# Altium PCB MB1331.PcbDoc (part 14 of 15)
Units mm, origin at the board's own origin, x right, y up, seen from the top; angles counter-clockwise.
Board outline 169.25 x 173.25 mm, 6 copper layers (Top Layer, Signal Layer 1, Signal Layer 2, Signal Layer 3, Signal Layer 4, Bottom Layer), stack 1.556 mm thick; 871 components, 699 nets, 3244 pads, 2370 vias.
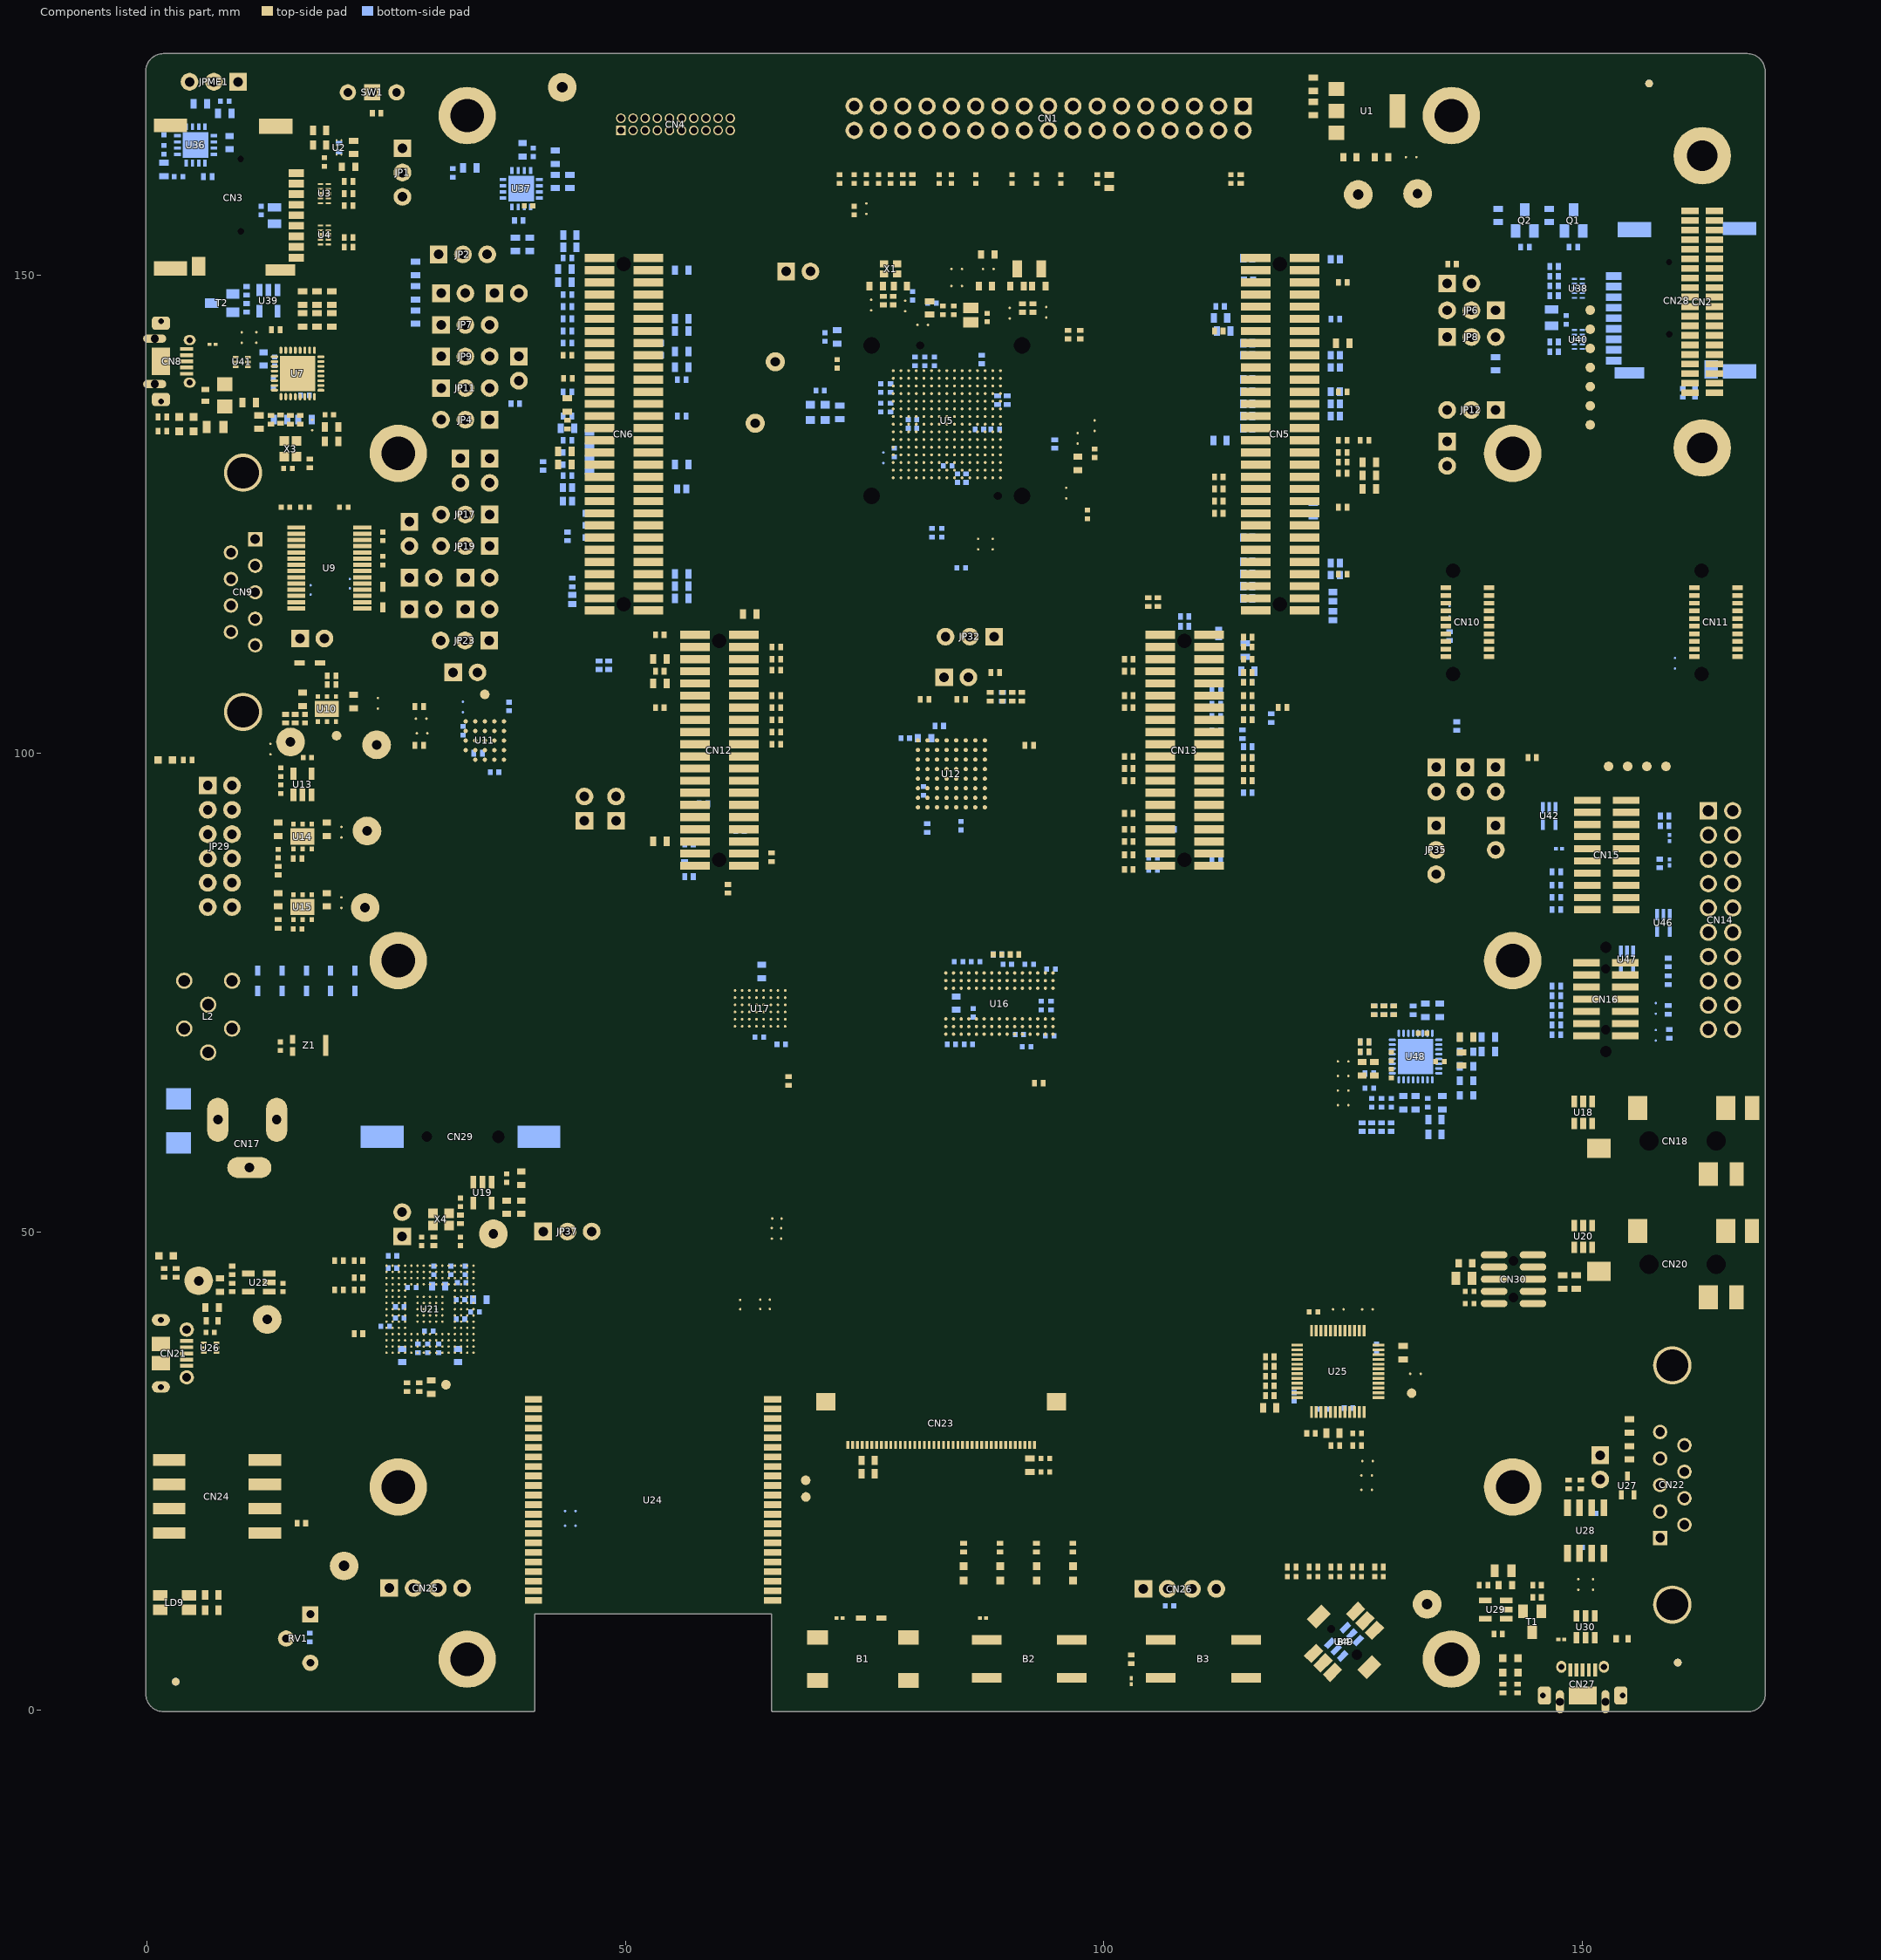
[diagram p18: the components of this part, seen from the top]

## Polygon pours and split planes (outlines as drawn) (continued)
5V_USB_HS on Top Layer "5V_USB_HS_L01_P1086" (solid, remove dead copper, pour order 1086): 5.969,134.874 6.604,134.874 6.731,134.747 6.731,134.493 6.731,132.842 6.604,132.715 5.715,132.715 5.588,132.842 5.588,133.35 5.588,134.747 5.715,134.874 5.969,134.874
NetC44_2 on Top Layer "NETC44_2_L01_P1068" (solid, remove dead copper, pour order 1068): 19.685,107.569 24.511,107.569 24.892,107.188 24.892,105.664 19.685,105.664 19.558,105.791 19.558,107.442
GND on Top Layer "GND_L01_P1080" (solid, remove dead copper, pour order 1080): 15.367,105.41 15.113,105.156 15.113,104.013 15.24,103.886 23.114,103.886 23.241,104.013 23.241,105.283 23.114,105.41
3V3_AO on Top Layer "3V3_AO_L01_P1084" (solid, remove dead copper, pour order 1084): 15.24,107.569 15.113,107.442 15.113,105.791 15.24,105.664 17.907,105.664 18.034,105.791 18.034,107.442 17.907,107.569
5V_D on Top Layer "5V_D_L01_P1087" (solid, remove dead copper, pour order 1087): 41.783,85.344 42.672,85.344 42.799,85.217 42.799,82.804 42.672,82.677 42.164,82.677 41.91,82.677 41.783,82.804 41.783,82.931 41.783,84.836
5V_USB_FS on Top Layer "5V_USB_FS_L01_P1090" (solid, remove dead copper, pour order 1090): 20.447,73.914 21.463,73.914 21.463,73.66 21.463,71.628 21.336,71.501 21.209,71.374 20.955,71.374 20.701,71.374 20.447,71.628 20.447,73.66
5V_USB_FS on Top Layer "5V_USB_FS_L01_P1093" (solid, remove dead copper, pour order 1093): 138.811,15.24 141.224,15.24 141.351,15.113 141.351,14.859 141.351,13.97 141.224,13.843 140.843,13.843 138.938,13.843 138.811,13.97 138.684,14.097 138.684,15.113 138.811,15.24
USB_OTG_FS_VBUS on Top Layer "USB_OTG_FS_VBUS_L01_P1095" (solid, remove dead copper, pour order 1095): 143.256,15.24 144.145,15.24 144.272,15.24 144.399,15.113 145.161,14.351 145.161,13.081 145.161,12.827 145.034,12.7 144.907,12.573 144.526,12.573 143.764,12.573 143.51,12.319 142.875,12.319 142.875,14.732 143.002,14.859
5V on Top Layer "5V_L01_P1098" (solid, remove dead copper, pour order 1098): 139.192,10.16 140.335,10.16 140.462,10.033 140.589,9.906 140.589,9.779 140.589,8.89 140.335,8.636 139.446,8.636 139.192,8.636 138.684,9.144 138.43,9.398 138.43,9.652 138.43,10.033 138.557,10.16 139.192,10.16
5V on Top Layer "5V_L01_P1101" (solid, remove dead copper, pour order 1101): 150.749,15.494 151.257,15.494 151.384,15.621 151.384,15.748 151.384,17.399 151.511,17.526 151.765,17.526 152.019,17.526 152.146,17.653 152.146,17.907 151.892,18.161 150.876,18.161 150.622,17.907 150.622,17.399 150.622,15.621 150.749,15.494
VDD_SMPS_IND_OUT on Top Layer "VDD_SMPS_IND_OUT_L01_P1069" (solid, remove dead copper, pour order 1069): 85.217,151.384 87.222,151.384 87.484,151.122 87.484,146.666 87.122,146.304 85.217,146.304 85.09,146.431 85.09,151.257
VDD_LDO on Top Layer "VDD_LDO_L01_P1074" (solid, remove dead copper, pour order 1074): 81.788,151.384 83.439,151.384 84.047,151.384 84.309,151.122 84.309,150.122 84.309,150.095 84.074,149.86 83.058,149.86 81.534,149.86 81.407,149.987 81.407,150.241 81.407,151.257 81.534,151.384 81.788,151.384
1V8_AO on Top Layer "1V8_AO_L01_P1081" (solid, remove dead copper, pour order 1081): 88.392,152.654 89.408,152.654 89.535,152.527 89.535,150.114 89.281,149.86 88.265,149.86 88.265,152.527
3V3_SMPS_IN on Top Layer "3V3_SMPS_IN_L01_P1085" (solid, remove dead copper, pour order 1085): 81.534,146.177 82.931,146.177 84.582,146.177 84.709,146.05 84.709,145.796 84.709,140.517 84.4,140.208 83.947,140.208 83.693,140.462 83.566,140.589 83.566,141.478 83.566,143.51 83.058,144.018 82.55,144.018 81.813,144.018 81.551,144.28 81.534,144.297 81.534,146.177
VCAP on Top Layer "VCAP_L01_P1088" (solid, remove dead copper, pour order 1088): 81.534,149.479 84.201,149.479 84.328,149.352 84.328,148.209 84.201,148.082 81.534,148.082 81.407,148.209 81.407,149.352
3V3_MCU on Top Layer "3V3_MCU_L01_P1091" (solid, remove dead copper, pour order 1091): 82.296,146.558 80.645,146.558 80.518,146.685 80.518,147.701 80.645,147.828 82.296,147.828 82.423,147.701 82.423,146.685
GND on Top Layer "GND_L01_P1070" (solid, remove dead copper, pour order 1070): 78,142 76.2,143.8 73.4,143.8 72.8,144.4 72.8,151.7 74,152.9 80.1,152.9 81.1,151.9 81.1,148.5 80.9,148.3 79.2,148.3 79,148.5 79,151.7 78.8,151.9 76.6,151.9 76.5,151.8 76.5,150.1 75.9,149.5 75.9,148.5 75.8,148.4 74.7,148.4 74.3,148 74.3,145.6 74.5,145.4 76.7,145.4 77.1,145 77.1,143.8 78.9,142
GND on Top Layer "GND_L01_P1075" (solid, remove dead copper, pour order 1075): 91,153 91.9,153 94.7,153 95.1,152.6 96.3,151.4 96.3,149.3 96.3,145.3 95.2,144.2 94.8,143.8 93.1,143.8 91.1,143.8 90.6,143.3 90.2,142.9 90.2,142.2 88.8,140.8 88.6,140.6 88.4,140.6 88.3,140.6 88.2,140.7 88.1,140.8 88.1,141.1 88.1,141.5 88.8,142.2 90.9,144.3 94.389,144.3 94.869,144.78 94.869,145.2 94.869,148.031 94.6,148.3 94.3,148.6 94.3,149.8 94.3,151.699 94.199,151.8 93.7,151.8 90.5,151.8 90.3,151.6 90.2,151.5 90.2,151.2 90.2,149.7 90.6,149.3 90.6,148.9 90.6,148.5 90.5,148.4 90.4,148.3 90.1,148.3 89.7,148.3 89.6,148.2 89.281,147.881 89.281,144.8 89.281,144.081 89,143.8 88.8,143.6 88.6,143.8 88.6,144.1 88.6,148.925 89.027,149.352 89.7,150.025 89.7,152.8 89.9,153 91,153
GND on Top Layer "GND_L01_P1152" (solid, remove dead copper, pour order 1152): 84.625,147.9 84.75,147.775 84.75,146.575 84.65,146.475 82.775,146.475 82.65,146.6 82.65,147.825 82.725,147.9
GND on Top Layer "GND_L01_P1154" (solid, remove dead copper, pour order 1154): 88.7,145.6 88.525,145.775 87.5,145.775 87.45,145.825 87.45,146.225 87.95,146.725 87.95,149.325 88.175,149.55 89.55,149.55 88.875,148.875 88.875,145.725 88.75,145.6
1V8_SW on Top Layer "1V8_SW_L01_P1073" (solid, remove dead copper, pour order 1073): 23.876,102.108 24.765,102.108 24.892,102.235 25.019,102.362 25.019,102.743 25.019,104.775 24.892,104.902 23.495,104.902 23.495,102.235 23.622,102.108 23.876,102.108
1V8_AO on Top Layer "1V8_AO_L01_P1079" (solid, remove dead copper, pour order 1079): 13.9,100.711 13.389,100.2 13.3,100.2 12.9,100.6 12.4,100.1 12.3,100.1 12,100.4 12,103.1 12.6,103.7 13.5,103.7 13.8,103.4 13.8,102.9 14,102.7 15.8,102.7 16,102.5 16.002,102 16.002,100.965 15.748,100.711
USB_OTG_FS_VBUS on Top Layer "USB_OTG_FS_VBUS_L01_P1115" (solid, remove dead copper, pour order 1115): 151.257,5.334 152.4,6.477 152.4,7.747 152.527,7.874 153.797,7.874 153.924,7.747 153.924,3.81 153.289,3.175 151.257,3.175
GND on Top Layer "GND_L01_P1118" (solid, remove dead copper, pour order 1118): 155.829,7.874 155.067,7.874 154.686,7.874 154.559,7.747 154.559,3.754 153.726,2.921 153.67,2.865 153.67,1.651 153.67,0.508 153.797,0.381 155.067,0.381 155.194,0.381 155.702,0.889 156.083,1.27 156.083,7.493 156.083,7.62 155.829,7.874
GND on Top Layer "GND_L01_P1121" (solid, remove dead copper, pour order 1121): 147.574,5.207 148.209,5.207 148.717,5.207 148.844,5.08 148.971,4.953 148.971,3.048 149.098,2.921 149.86,2.921 154.686,2.921 154.813,2.794 154.813,2.286 154.813,0.635 154.559,0.381 153.924,0.381 145.542,0.381 145.288,0.635 145.288,1.016 145.288,2.921 147.574,5.207
USB_OTG_FS_VBUS on Top Layer "USB_OTG_FS_VBUS_L01_P1127" (solid, remove dead copper, pour order 1127): 142.367,15.24 143.256,15.24 143.51,14.986 143.51,11.684 143.002,11.176 141.605,11.176 141.478,11.303 141.478,11.938 142.113,12.573 142.113,14.986
3V3_AO on Top Layer "3V3_AO_L01_P1131" (solid, remove dead copper, pour order 1131): 19.685,83.6 18.8,82.715 18.8,81.3 19,81.1 22.1,81.1 24.4,83.4 24.4,84.7 23.6,85.5 21.6,85.5 20.2,84.074 19.812,84.074 19.685,83.947
3V3_SW on Top Layer "3V3_SW_L01_P1133" (solid, remove dead copper, pour order 1133): 19.685,91.985 19.8,92.1 20.3,91.6 20.9,92.2 21.2,92.2 22.5,93.5 23.9,93.5 24.6,92.8 24.6,90.3 22.32,87.979 22.225,87.884 19.812,87.884 19.685,88.011
NetC53_2 on Top Layer "NETC53_2_L01_P1135" (solid, remove dead copper, pour order 1135): 16.256,86.614 20.828,86.614 21.082,86.36 21.082,84.963 16.129,84.963 16.002,85.09 16.002,86.36
5V_STLK on Top Layer "5V_STLK_L01_P1136" (solid, remove dead copper, pour order 1136): 14.859,40.159 14,39.3 11.6,39.3 10.9,40 10.9,41.904 12.065,43.104 12.065,43.942 12.192,44.069 14.732,44.069 14.859,43.942
3V3_STLK on Top Layer "3V3_STLK_L01_P1137" (solid, remove dead copper, pour order 1137): 37.405,48.2 35.4,48.2 34.5,49.1 34.5,50.7 35.687,51.9 35.687,53.467 35.814,53.594 36.576,53.594 36.703,53.467 36.703,52.832 36.957,52.578 39.497,52.578 39.624,52.451 39.624,50.419
GND on Top Layer "GND_L01_P1142" (solid, remove dead copper, pour order 1142): 18.034,84.709 13.335,84.709 13.208,84.582 13.208,84.328 13.208,83.439 13.335,83.312 13.462,83.185 15.494,83.185 19.177,83.185 19.304,83.312 19.304,83.566 19.304,84.582 19.177,84.709 18.034,84.709
5V_EXT_UNFILT on Top Layer "5V_EXT_UNFILT_L01_P1092" (solid, remove dead copper, pour order 1092): 14.986,73.406 15.621,72.771 15.621,69.85 15.367,69.596 8.636,69.596 8.128,70.104 8.128,73.025 8.509,73.406
5V_EXT_CONN on Top Layer "5V_EXT_CONN_L01_P1094" (solid, remove dead copper, pour order 1094): 21.082,58.928 21.59,59.436 21.59,69.596 19.812,71.374 17.78,71.374 17.272,70.866 17.272,65.405 16.764,64.897 12.573,64.897 12.065,64.389 12.065,59.182 12.319,58.928
GND_EXT_UNFILT on Top Layer "GND_EXT_UNFILT_L01_P1097" (solid, remove dead copper, pour order 1097): 12.573,54.991 3.302,54.991 2.54,55.753 2.54,56.134 2.54,66.294 3.175,66.929 3.429,67.183 3.81,67.183 6.985,67.183 7.874,68.072 9.144,69.342 14.605,69.342 15.494,69.342 15.621,69.215 15.621,69.088 15.621,65.786 15.367,65.532 14.605,65.532 11.811,65.532 11.303,65.024 11.049,64.77 11.049,64.643 11.049,58.674 11.43,58.293 11.811,58.293 13.081,58.293 13.462,57.912 13.462,57.531 13.462,55.245 13.208,54.991 12.573,54.991
5V_USB_CHGR on Top Layer "5V_USB_CHGR_L01_P1132" (solid, remove dead copper, pour order 1132): 3.524,38.386 5.143,38.386 5.558,38.8 6.257,38.8 6.477,39.02 6.572,39.02 6.572,42.481 6.953,42.862 10.763,42.862 11.239,43.339 11.239,44.005 11.144,44.101 5.715,44.101 5.429,43.815 5.429,39.719 4.667,38.957 3.524,38.957 3.429,38.862 3.429,38.481
5V on Top Layer "5V_L01_P1145" (solid, remove dead copper, pour order 1145): 8.763,82.931 10.668,82.931 11.557,82.931 11.811,83.185 11.811,83.566 11.811,97.409 11.557,97.663 8.89,97.663 8.255,97.663 8.001,97.409 8.001,96.901 8.001,83.185 8.255,82.931 8.763,82.931
5V_LCD on Top Layer "5V_LCD_L01_P1178" (solid, remove dead copper, pour order 1178): 138.128,47.45 137.875,47.197 137.875,43.55 138.2,43.225 142.175,43.225 142.6,43.65 142.6,45.576 141.551,46.625 139.725,46.625 138.9,47.45
GND on Top Layer "GND_L01_P1180" (solid, remove dead copper, pour order 1180): 1.143,172.466 167.64,172.466 168.656,171.45 168.656,1.651 167.64,0.635 1.524,0.635 0.381,1.778 0.381,171.704
3V3_OCSPI1 on Signal Layer 2 "3V3_OCSPI1_L03_P1107" (solid, remove dead copper, pour order 1107): 38.1,106.045 38.481,105.664 38.481,98.298 37.719,97.536 32.131,97.536 30.988,98.679 30.988,105.791 31.242,106.045
1V8_CODEC on Signal Layer 2 "1V8_CODEC_L03_P1065" (solid, remove dead copper, pour order 1065): 132.715,72.009 134.493,72.009 135.001,72.009 135.509,71.501 135.89,71.12 135.89,69.723 135.89,65.405 135.255,64.77 134.747,64.262 133.985,64.262 127.889,64.262 127.381,64.77 127,65.151 127,71.755 127.254,72.009 132.715,72.009
5V on Signal Layer 2 "5V_L03_P1104" (solid, remove dead copper, pour order 1104): 143.51,10.16 150.368,17.018 150.368,17.907 150.622,18.161 151.892,18.161 152.146,17.907 152.146,16.383 144.399,8.636 138.557,8.636 138.43,8.763 138.43,10.033 138.557,10.16
3V3_STLK on Signal Layer 2 "3V3_STLK_L03_P1143" (solid, remove dead copper, pour order 1143): 24.892,51.054 24.257,50.419 24.257,45.593 24.765,45.085 24.765,34.925 25.527,34.163 33.528,34.163 39.497,40.132 39.497,50.419 38.862,51.054
5V_USB_HS on Signal Layer 2 "5V_USB_HS_L03_P1100" (solid, remove dead copper, pour order 1100): 6.604,92.583 5.461,92.583 4.826,92.583 4.572,92.837 4.445,92.964 4.445,93.091 4.445,128.524 6.731,130.81 6.731,132.715 6.731,133.35 6.604,133.477 5.715,133.477 5.588,133.35 5.588,133.223 5.588,131.318 5.207,130.937 3.175,128.905 3.175,128.016 3.175,91.44 3.556,91.059 4.064,90.551 5.588,90.551 6.858,90.551 7.112,90.551 7.366,90.805 7.366,91.44 7.366,92.202 7.112,92.456 6.985,92.583 6.604,92.583
GND_EXT_UNFILT on Signal Layer 2 "GND_EXT_UNFILT_L03_P1103" (solid, remove dead copper, pour order 1103): 11.303,77.343 13.589,75.057 13.589,66.421 13.335,66.167 10.541,66.167 10.287,66.421 10.287,72.39 8.001,74.676 8.001,76.962 8.382,77.343
GND on Signal Layer 2 "GND_L03_P1184" (solid, remove dead copper, pour order 1184): 1.143,172.466 167.64,172.466 168.656,171.45 168.656,1.651 167.64,0.635 1.524,0.635 0.381,1.778 0.381,171.704
5V on Signal Layer 3 "5V_L04_P1162" (solid, remove dead copper, pour order 1162): 167.005,1.397 167.767,2.159 167.767,170.307 166.37,171.704 121.412,171.704 45.7,171.7 45.4,171.4 45.4,160.9 44.8,160.3 14.1,160.3 10.8,157 10.8,134.8 11.1,134.5 18.034,134.493 18.415,134.874 18.415,152.908 21.59,156.083 62.4,156.1 62.6,156.3 62.6,166.2 62.9,166.5 119.9,166.5 121.031,165.369 121.031,159.766 121.412,159.385 156.337,159.385 158.496,157.226 158.496,19.431 157.607,18.542 74.676,18.542 67.564,25.654 67.564,39.497 66.929,40.132 46.355,40.132 45.085,38.862 45.085,18.669 44.958,18.542 23.114,18.542 19.05,22.606 19.05,83.312 11.938,90.424 11.938,97.028 11.049,97.917 8.128,97.917 8.001,97.79 8.001,16.51 12.573,11.938 66.421,11.938 76.962,1.397
3V3_AO on Signal Layer 3 "3V3_AO_L04_P1064" (solid, remove dead copper, pour order 1064): 19.864,83.3 18.8,83.3 18.5,83 18.5,81.4 19.812,80.1 19.812,23.05 23.812,19.05 44.45,19.05 44.704,19.304 44.704,38.989 45.593,39.878 46.355,40.64 67.056,40.64 67.945,39.751 67.945,26.113 75.008,19.05 156.591,19.05 158.115,20.574 158.115,156.21 156.337,157.988 121.158,157.988 120.015,159.131 120.015,164.973 118.999,165.989 63.5,166 63.1,165.6 63.1,156 63.3,155.8 66.3,155.8 68,154.1 68,152.5 68.1,152.4 96.139,152.4 98.87,149.669 98.87,120.968 96.584,118.681 68.199,118.681 67.627,119.253 67.627,153.987 66.167,155.448 22.098,155.448 19.241,152.59 19.241,113.728 15.24,109.728 15.24,106.87 24.003,98.108 24.003,93.997 25,93 25,88.4 23.882,87.318
3V3_SW on Signal Layer 3 "3V3_SW_L04_P1182" (solid, remove dead copper, pour order 1182): 22.987,94.413 24.7,92.7 24.7,89.7 22.987,88.011 22.352,87.376 15.748,87.376 12.446,90.678 12.446,97.409 1.397,108.458 1.397,170.307 2.286,171.196 8.763,171.196 40.9,171.2 44.3,171.2 44.8,170.7 44.8,161 44.6,160.8 13.97,160.782 10.414,157.226 10.414,134.239 10.922,133.731 18.034,133.731 18.415,133.35 18.415,114.046 14.478,110.109 14.478,106.553 22.987,98.044
VDD_LDO on Signal Layer 3 "VDD_LDO_L04_P1166" (solid, remove dead copper, pour order 1166): 80.391,128.27 79.883,128.778 79.883,132.207 80.264,132.581 82.176,132.581 84.328,130.429 88.138,130.429 89.408,131.699 89.408,136.398 88.631,137.175 85.271,137.175 85.269,136.927 84.742,136.927 83.873,137.795 83.873,149.68 83.693,149.86 81.534,149.86 81.407,149.987 81.407,151.511 81.661,151.765 92.837,151.765 92.964,151.638 92.964,131.064 90.17,128.27
3V3_MCU on Signal Layer 3 "3V3_MCU_L04_P1168" (solid, remove dead copper, pour order 1168): 80.01,132.842 79.502,132.334 79.502,128.651 80.264,127.889 90.297,127.889 91.821,129.413 97.868,129.413 98.298,128.983 98.298,121.285 96.139,119.126 68.453,119.126 68.072,119.507 68.072,150.622 69.215,151.765 80.899,151.765 81.026,151.638 81.026,146.05 81.016,146.04 81.026,146.031 81.026,141.859 78.232,139.065 78.232,134.747 78.74,134.239 81.915,134.239 82.042,134.366 82.042,135.001 81.842,135.201 81.575,135.201 81.406,135.369 81.406,135.762 81.534,135.89 82.931,135.89 83.185,135.636 83.947,135.636 84.201,135.89 85.725,135.89 85.961,135.654 85.961,135.146 85.979,135.128 85.979,133.096 85.598,132.715 80.998,132.715 80.871,132.842
VCAP on Signal Layer 3 "VCAP_L04_P1170" (solid, remove dead copper, pour order 1170): 81.534,141.859 78.613,138.938 78.613,134.874 78.994,134.493 81.026,134.493 81.153,134.366 81.661,134.366 81.788,134.493 81.788,134.819 81.153,135.454 81.153,135.882 81.407,136.136 83.066,136.136 83.312,135.89 86.233,135.89 86.233,132.969 85.725,132.461 83.82,132.461 83.693,132.334 83.693,131.445 84.201,130.937 87.884,130.937 89.027,132.08 89.027,136.144 88.575,136.596 88.575,136.652 88.268,136.652 88.268,137.033 83.566,137.033 83.566,149.225 83.185,149.606 81.788,149.606 81.534,149.352
5V_EXT on Signal Layer 3 "5V_EXT_L04_P1130" (solid, remove dead copper, pour order 1130): 0.381,70.231 0.386,70.231 0.64,69.968 4.826,69.968 5.08,70.231 5.08,72.263 2.907,74.436 2.907,92.95 3,93.043 6.942,93.043 7,92.985 7.112,93.097 7.112,95.305 0.39,95.305 0.381,95.296
3V3_MCU on Bottom Layer "3V3_MCU_L06_P1126" (solid, remove dead copper, pour order 1126): 79.756,147.828 81.788,147.828 81.915,147.701 81.915,146.685 81.788,146.558 79.756,146.558 79.629,146.685 79.629,147.701
NetR202_1 on Bottom Layer "NETR202_1_L06_P1111" (solid, remove dead copper, pour order 1111): 2.413,162.687 2.413,162.306 2.286,162.179 1.397,162.179 1.27,162.052 1.27,161.417 1.397,161.29 3.048,161.29 3.556,161.798 3.556,162.687 3.429,162.814 2.54,162.814
3V3_SW on Bottom Layer "3V3_SW_L06_P1113" (solid, remove dead copper, pour order 1113): 3.048,160.782 3.175,160.655 3.175,157.988 3.048,157.861 1.524,157.861 1.27,158.115 1.27,160.655 1.397,160.782
GND on Bottom Layer "GND_L06_P1119" (solid, remove dead copper, pour order 1119): 3.683,160.782 4.572,160.782 4.699,160.655 5.461,159.893 5.461,159.385 5.461,158.115 5.334,157.988 5.207,157.861 3.937,157.861 3.683,157.861 3.556,157.861 3.429,157.988 3.429,160.528 3.683,160.782
5V_STLK_LDO_IN on Bottom Layer "5V_STLK_LDO_IN_L06_P1122" (solid, remove dead copper, pour order 1122): 11.147,74.742 11.147,75.885 11.274,76.012 11.401,76.012 22.069,76.012 22.196,75.885 22.196,75.25 22.196,74.361 22.069,74.234 21.815,74.234 11.274,74.234 11.147,74.361 11.147,74.742
5V_STLK_LDO_IN on Bottom Layer "5V_STLK_LDO_IN_L06_P1105" (solid, remove dead copper, pour order 1105): 22.098,73.914 23.114,73.914 23.114,73.533 23.114,71.628 23.114,71.501 22.987,71.374 22.225,71.374 22.098,71.501 22.098,73.914
USB_OTG_FS_VBUS on Bottom Layer "USB_OTG_FS_VBUS_L06_P1147" (solid, remove dead copper, pour order 1147): 144.5,12.7 144.838,12.362 144.838,11.038 142.9,9.1 142.9,8.4 144.8,6.5 147.1,6.477 153.797,6.477 153.924,6.604 153.924,7.747 153.797,7.874 147.066,7.874 146.431,8.509 146.431,13.081 145.034,14.478 143.256,14.478 143.002,14.224 143.002,12.827 143.129,12.7
5V on Bottom Layer "5V_L06_P1128" (solid, remove dead copper, pour order 1128): 12.319,144.907 11.303,144.907 11.176,145.034 11.049,145.161 11.049,145.542 11.049,146.812 11.176,146.939 11.938,146.939 12.192,146.685 12.319,146.558 12.319,146.177 12.319,145.796 12.573,145.542 12.7,145.415 12.7,145.161 12.7,145.034 12.573,144.907 12.319,144.907
3V3_MCU on Bottom Layer "3V3_MCU_L06_P1076" (solid, remove dead copper, pour order 1076): 77.7,130.3 77.7,129.9 77.537,129.737 77.462,129.737 73.537,129.737 73.4,129.6 73.2,129.4 71.8,129.4 71.6,129.6 71.6,129.8 71.6,130 72,130.4 72.5,130.9 75.2,130.9 76.2,130.9 76.4,130.7 76.688,130.412 77.462,130.412 77.588,130.412 77.7,130.3
VCAP on Bottom Layer "VCAP_L06_P1172" (solid, remove dead copper, pour order 1172): 89.281,135.763 85.725,135.763 83.566,133.604 80.264,133.604 80.137,133.731 80.137,134.239 80.264,134.366 80.899,134.366 81.661,135.128 82.55,135.128 84.963,137.541 87.659,137.541 88.421,136.779 89.281,136.779 89.408,136.652 89.408,135.89
3V3_MCU on Bottom Layer "3V3_MCU_L06_P1174" (solid, remove dead copper, pour order 1174): 81.28,133.35 83.82,133.35 84.582,134.112 86.614,134.112 86.741,133.985 86.741,133.35 86.233,132.842 81.28,132.842
NetC86_2 on Bottom Layer "NETC86_2_L06_P1108" (solid, remove dead copper, pour order 1108): 6.731,171.196 7.62,171.196 7.747,171.196 7.874,171.069 8.001,170.942 8.001,168.021 8.001,165.354 7.874,165.227 7.747,165.1 6.35,165.1 5.969,165.1 5.842,165.227 5.842,167.005 5.842,170.815 6.223,171.196 6.731,171.196
NetJPME1_3 on Bottom Layer "NETJPME1_3_L06_P1109" (solid, remove dead copper, pour order 1109): 4.953,165.227 4.953,166.624 5.461,167.132 5.461,170.942 5.207,171.196 3.048,171.196 2.794,170.942 2.794,167.513 3.048,167.259 4.191,167.259 4.572,166.878 4.572,165.1 4.826,165.1
GND on Bottom Layer "GND_L06_P1116" (solid, remove dead copper, pour order 1116): 10.795,171.196 11.049,170.942 11.049,166.37 10.922,166.243 8.509,166.243 8.255,166.497 8.255,170.942 8.509,171.196
5V on Bottom Layer "5V_L06_P1164" (solid, remove dead copper, pour order 1164): 17.018,95.123 8.255,95.123 8.001,94.869 8.001,93.599 8.382,93.218 16.764,93.218 20.32,96.774 22.479,96.774 22.606,96.901 22.606,97.536 22.352,97.79 19.685,97.79
GND on Bottom Layer "GND_L06_P1186" (solid, remove dead copper, pour order 1186): 1.143,172.466 167.64,172.466 168.656,171.45 168.656,1.651 167.64,0.635 1.524,0.635 0.381,1.778 0.381,171.704
GND on Signal Layer 1 "GND_L02_P1149" (solid, remove dead copper, pour order 1149): 167.64,172.466 168.656,171.45 168.656,1.651 167.64,0.635 1.524,0.635 0.381,1.778 0.381,171.704 1.143,172.466
GND on Signal Layer 4 "GND_L05_P1150" (solid, remove dead copper, pour order 1150): 167.64,172.466 168.656,171.45 168.656,1.651 167.64,0.635 1.524,0.635 0.381,1.778 0.381,171.704 1.143,172.466

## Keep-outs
Keep-Out Layer:
  rectangle: 145,169.425 153.5,171.175
  lines w0.203: 0,1.5 ccw(c1.5,1.5) 1.5,0 167.5,0 ccw(c167.5,1.5) 169,1.5 169,171.5 ccw(c167.5,171.5) 167.5,173 1.5,173 ccw(c1.5,171.5) 0,171.5 0,1.5

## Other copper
Top Layer:
  text "1" at 145.25,169.675 h2
Signal Layer 1:
  text "2" at 146.5,169.675 h2
Signal Layer 2:
  text "3" at 148,169.675 h2
Signal Layer 3:
  text "4" at 150.25,169.675 h2
Signal Layer 4:
  text "5" at 151.75,169.675 h2
Bottom Layer:
  pour cut-out: 90.25,23.75 90.15,23.65 90.15,23.15 90.35,22.95 103.175,22.95 113.275,33.05 113.275,66.2 131.15,84.075 131.15,122.925 129.025,125.05 129.025,137.915 129.65,138.54 129.65,150.05 126.775,152.925 126.325,152.925 125.8,152.4 125.8,151.695 127.7,149.795 127.7,124.775 129.975,122.5 129.975,84.2 112.3,66.525 112.3,33.575 102.475,23.75
  text "6" at 153.25,169.675 h2

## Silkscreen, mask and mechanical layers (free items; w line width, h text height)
Top Overlay:
  drawing of 531 lines, arcs and shapes, not listed
  text "0=Flash" at 34.798,171.577 h1.5
  text "MB1299" at 52.715,171.5 h1.5
  text "MB1379" at 160.02,171.45 h1.5
  text "MOTOR CONTROL" at 86.594,171.2 h2
  text "STMPS2" at 11.6,171.1 h1.5
  text "0" at 21.498,171.035 h2
  text "1" at 24.998,171.035 h2
  text "BOOT0" at 27.953,170.908 h2
  text "1=Sys mem" at 34.798,170.053 h1.5
  text "POWER" at 11.6,169.9 h1.5
  text "METER" at 11.6,168.8 h1.5
  text "uSD2" at 0.7,166.9 h2
  text "GND" at 42.264,164.873 h1.4
  text "CAMERA" at 149.6,161 h2
  text "GND" at 121.704,158.073 h1.4
  text "DFSDM AUDIO & MOTOR" at 47.235,157.3 h1.5
  text "SDIO2/DCMI" at 29.575,157.1 h1.4 r90
  text "2V8" at 131.69,155.217 h1.6
  text "SRAM/SDIO2" at 29.2,153.8 h1.4
  text "3V3 MCU" at 65.405,152.4 h1.4
  text "PC2_C" at 58.61,151.765 h1.4
  text "PI12" at 108.025,151.765 h1.4
  text "PI13" at 129.54,151.765 h1.4
  text "PC1" at 54.88,151.565 h1.4
  text "J" at 98.8,151 h15
  text "PC15" at 108.025,150.495 h1.4
  text "PC14" at 129.54,150.495 h1.4
  text "PC3_C" at 58.593,150.346 h1.4
  text "PH0" at 54.88,150.295 h1.4
  text "POT PA0_C" at 35.179,149.733 h1.4
  text "EXT ANA" at 29.337,149.606 h1.4
  text "PI14" at 108.025,149.225 h1.4
  text "PC13" at 129.54,149.225 h1.4
  text "PH1_E" at 58.593,149.076 h1.4
  text "NRST" at 54.9,149 h1.4
  text "SDIO1" at 140.208,148.717 h1.4
  text "PF10" at 108.025,147.955 h1.4
  text "PI8" at 129.54,147.955 h1.4
  text "PA0" at 58.593,147.806 h1.4
  text "PF7" at 54.88,147.755 h1.4
  text "PB9" at 108.025,146.685 h1.4
  text "GND" at 129.54,146.685 h1.4
  text "USB / OTG HS" at 1.6,146.6 h2
  text "GND" at 58.593,146.536 h1.4
  text "PF6" at 54.88,146.485 h1.4
  text "I2S6/DCMI" at 143.129,146.177 h1.4
  text "PB8" at 107.985,145.415 h1.4
  text "PA6" at 129.54,145.415 h1.4
  text "PA1" at 58.593,145.266 h1.4
  text "PF8" at 54.88,145.215 h1.4
  text "uSD1" at 167.9,144.832 h2 r90
  text "I2S6/DCMI" at 37.5,144.5 h1.4
  text "PB7" at 107.985,144.145 h1.4
  text "PB4" at 129.54,144.145 h1.4
  text "PA2" at 58.593,143.996 h1.4
  text "PF9" at 54.88,143.945 h1.4
  text "I2S6/JTAG" at 142.875,143.256 h1.4
  text "PK6" at 107.985,142.875 h1.4
  text "PB3" at 129.54,142.875 h1.4
  text "VREFP" at 63.536,142.801 h1.4
  text "PA0_C" at 58.593,142.726 h1.4
  text "PC2" at 54.9,142.6 h1.4
  text "PK5" at 108.025,141.605 h1.4
  text "PK7" at 129.54,141.605 h1.4
  text "PA1_C" at 58.593,141.456 h1.4
  text "PB6" at 54.9,141.4 h1.4
  text "GND" at 108.025,140.335 h1.4
  text "PK4" at 129.54,140.335 h1.4
  text "GND" at 54.8,140.2 h1.2
  text "PC0" at 58.593,140.186 h1.4
  text "PK3" at 108.025,139.065 h1.4
  text "PG13" at 129.54,139.065 h1.4
  text "PA4" at 55,139 h1.2
  text "PG11" at 58.593,138.916 h1.4
  text "A" at 24.446,138.43 h1.6
  text "USBHS" at 41.572,138.172 h1.4 r90
  text "SRAM/SDIO1" at 134.6,137.9 h1.4
  text "PJ2" at 108.025,137.795 h1.4
  text "PJ12" at 129.54,137.795 h1.4
  text "PH5" at 58.593,137.646 h1.4
  text "PC3" at 54.7,137.5 h1.4
  text "VDDA" at 63.405,136.55 h1.4
  text "PJ4" at 108.025,136.525 h1.4
  text "PJ13" at 129.54,136.525 h1.4
  text "PA3" at 58.593,136.376 h1.4
  text "I2S6/" at 38.35,136.275 h1.4
  text "PH2" at 54.8,136.1 h1.4
  text "USBHS" at 38.325,135.25 h1.4
  text "PJ1" at 108.025,135.255 h1.4
  text "PJ14" at 129.54,135.255 h1.4
  text "PB0" at 58.593,135.106 h1.4
  text "PH3" at 54.77,135.055 h1.4
  text "PJ15" at 108.025,133.985 h1.4
  text "GND" at 129.54,133.985 h1.4
  text "SDIO2/" at 38.325,133.875 h1.3
  text "GND" at 58.593,133.836 h1.4
  text "PH4" at 54.77,133.785 h1.4
  text "OCSPI1" at 38.325,132.925 h1.3
  text "A" at 8.382,132.715 h1.6
  text "PD2" at 108.025,132.715 h1.4
  text "PD3" at 129.54,132.715 h1.4
  text "PB2" at 58.593,132.566 h1.4
  text "PA5" at 54.77,132.515 h1.4
  text "PC12" at 107.95,131.445 h1.4
  text "PC11" at 129.54,131.445 h1.4
  text "PG12" at 58.593,131.296 h1.4
  text "PC4" at 54.77,131.245 h1.4
  text "PC10" at 107.95,130.175 h1.4
  text "PA15" at 129.54,130.175 h1.4
  text "PD6" at 58.593,130.026 h1.4
  text "PC5" at 54.77,129.975 h1.4
  text "uSD1" at 150.749,129.159 h2
  text "PA14" at 107.95,128.905 h1.4
  text "PA13" at 129.54,128.905 h1.4
  text "PD7" at 58.593,128.756 h1.4
  text "PI15" at 54.77,128.705 h1.4
  text "GND" at 107.95,127.635 h1.4
  text "PA10" at 129.54,127.635 h1.4
  text "(bottom)" at 150.749,127.635 h2
  text "PJ3" at 58.593,127.486 h1.4
  text "SDIO2" at 31.1,127.4 h1.4 r90
  text "GND" at 54.664,127.381 h1.4
  text "USBHS" at 38.4,127.1 h1.4 r90
  text "SAI" at 135.001,127 h1.4
  text "PA12" at 107.95,126.365 h1.4
  text "PB10" at 58.593,126.216 h1.4
  text "PJ0" at 54.8,126.2 h1.4
  text "I2S6" at 26.289,125.857 h1.4
  text "PA9" at 128.27,125.857 h1.4
  text "PB1" at 54.845,125.095 h1.4
  text "PA11" at 107.95,125.095 h1.4
  text "PB11" at 58.593,124.946 h1.4
  text "PC8" at 128.27,124.841 h1.4
  text "SDIO2/DCMI" at 37.346,124.622 h1.4
  text "PI11" at 54.845,123.825 h1.4
  text "PC9" at 107.95,123.825 h1.4
  text "PG7" at 128.27,123.825 h1.4
  text "PB5" at 58.593,123.676 h1.4
  text "PG14" at 54.845,122.555 h1.4
  text "PK1" at 107.95,122.555 h1.4
  text "3V3" at 128.27,122.555 h1.4
  text "3V3" at 58.593,122.406 h1.4
  text "USBHS/DFSDM" at 37.4,121.3 h1.2
  text "5V_D" at 54.845,121.285 h1.4
  text "5V_D" at 107.95,121.285 h1.4
  text "GND" at 128.27,121.285 h1.4
  text "GND" at 58.593,121.136 h1.4
  text "PG9" at 54.845,120.015 h1.4
  text "PK2" at 108.125,120.015 h1.4
  text "PJ11" at 128.27,120.015 h1.4
  text "PB12" at 58.593,119.866 h1.4
  text "PA8" at 54.845,118.745 h1.4
  text "PJ8" at 108.125,118.745 h1.4
  text "PK0" at 128.27,118.745 h1.4
  text "PB14" at 58.593,118.596 h1.4
  text "PJ5" at 54.845,117.475 h1.4
  text "PJ9" at 108.125,117.475 h1.4
  text "PJ10" at 128.27,117.475 h1.4
  text "VCP=PB14/5" at 37.6,117.4 h1.5
  text "PB15" at 58.593,117.326 h1.4
  text "PG6" at 54.845,116.205 h1.4
  text "PJ7" at 108.125,116.205 h1.4
  text "PJ6" at 128.27,116.205 h1.4
  text "PB13" at 58.593,116.056 h1.4
  text "GND" at 54.845,114.935 h1.4
  text "GND" at 108.125,114.935 h1.4
  text "5V" at 128.27,114.935 h1.4
  text "5V" at 58.593,114.786 h1.4
  text "OCSPI2" at 147.4,114.2 h2
  text "VCP=PA3/2" at 37.8,114 h1.5
  text "NOR/DCMI" at 83.1,114 h1.4
  text "MB1242" at 147.625,112.275 h2
  text "PH6" at 48.895,111.76 h1.4
  text "PA7" at 70.485,111.76 h1.4
  text "PF5" at 95.25,111.76 h1.4
  text "PH7" at 122.555,111.76 h1.4
  text "BL_RST" at 20.193,111.252 h1.4
  text "SDIO2/OCSP1" at 38.1,111.2 h1.4
  text "PF13" at 48.895,110.49 h1.4
  text "PF4" at 95.25,110.49 h1.4
  text "PE5" at 122.555,110.49 h1.4
  text "PF14" at 70.468,110.341 h1.4
  text "NOR_WP" at 81.534,109.728 h1.4
  text "PF12" at 48.895,109.22 h1.4
  text "PF3" at 95.25,109.22 h1.4
  text "PC6" at 122.555,109.22 h1.4
  text "PG0" at 70.468,109.071 h1.4
  text "RS232 UART BL" at 14.224,108.966 h1.5 r90
  text "BOOT0" at 36.254,108.063 h1.4
  text "PG1" at 48.895,107.95 h1.4
  text "PE6" at 95.25,107.95 h1.4
  text "PF2" at 122.555,107.95 h1.4
  text "PF11" at 70.468,107.801 h1.4
  text "GND" at 48.895,106.68 h1.4
  text "GND" at 95.25,106.68 h1.4
  text "GND" at 122.555,106.68 h1.4
  text "GND" at 70.468,106.531 h1.4
  text "PE7" at 48.895,105.41 h1.4
  text "PE4" at 95.25,105.41 h1.4
  text "PF1" at 122.555,105.41 h1.4
  text "PE9" at 70.468,105.261 h1.4
  text "PE10" at 48.895,104.14 h1.4
  text "PE3" at 95.25,104.14 h1.4
  text "PF0" at 122.555,104.14 h1.4
  text "PE8" at 70.468,103.991 h1.4
  text "PE12" at 48.895,102.87 h1.4
  text "PI5" at 95.25,102.87 h1.4
  text "PE2" at 122.555,102.87 h1.4
  text "PE11" at 70.468,102.721 h1.4
  text "1V8 SW" at 26.382,102.557 h1.6 r90
  text "PE15" at 48.895,101.6 h1.4
  text "PI4" at 95.25,101.6 h1.4
  text "PI7" at 122.555,101.6 h1.4
  text "PF15" at 70.468,101.451 h1.4
  text "PE13" at 48.895,100.33 h1.4
  text "PG15" at 95.25,100.33 h1.4
  text "PI9" at 122.555,100.33 h1.4
  text "PE14" at 70.468,100.181 h1.4
  text "PD11" at 48.895,99.06 h1.4
  text "PI10" at 95.25,99.06 h1.4
  text "PI6" at 122.555,99.06 h1.4
  text "1V8 AO" at 17.9,99 h1.6
  text "PH8" at 70.468,98.911 h1.4
  text "PD12" at 48.895,97.79 h1.4
  text "PE1" at 95.25,97.79 h1.4
  text "PC7" at 122.555,97.79 h1.4
  text "PH10" at 70.468,97.641 h1.4
  text "PG5" at 50.546,96.774 h1.4
  text "OCSPI1" at 33.254,96.763 h1.4
  text "PE0" at 95.25,96.52 h1.4
  text "PD5" at 122.555,96.52 h1.4
  text "PH9" at 70.468,96.371 h1.4
  text "STLK" at 0.762,96.091 h1.6
  text "PH11" at 50.546,95.758 h1.4
  text "PG10" at 95.25,95.25 h1.4
  text "PD4" at 122.555,95.25 h1.4
  text "PG4" at 70.468,95.101 h1.4
  text "SAI" at 143.129,94.869 h1.4
  text "GND" at 50.419,94.488 h1.4
  text "3V3 SW" at 20.588,94.274 h1.6
  text "GND" at 95.25,93.98 h1.4
  text "GND" at 122.555,93.98 h1.4
  text "GND" at 70.468,93.831 h1.4
  text "ADCP/N" at 38.735,93.726 h1.4
  text "EXT" at 1.27,93.514 h1.6
  text "PD13" at 50.546,92.964 h1.4
  text "PD0" at 95.25,92.71 h1.4
  text "PD1" at 122.555,92.71 h1.4
  text "PH12" at 70.468,92.561 h1.4
  text "PG2" at 50.546,91.694 h1.4
  text "PI2" at 95.25,91.44 h1.4
  text "PI3" at 122.555,91.44 h1.4
  text "PG3" at 70.468,91.291 h1.4
  text "HS" at 1.651,91.059 h1.6
  text "NOR" at 82.254,90.763 h1.4
  text "PD8" at 48.895,90.17 h1.4
  text "PI1" at 95.25,90.17 h1.4
  text "PH15" at 122.555,90.17 h1.4
  text "5V" at 10.905,90.159 h1.6
  text "PD10" at 70.468,90.021 h1.4
  text "PD9" at 48.895,88.9 h1.4
  text "PI0" at 95.25,88.9 h1.4
  text "PH14" at 122.555,88.9 h1.4
  text "PD15" at 70.468,88.751 h1.4
  text "FS" at 1.651,88.519 h1.6
  text "PD14" at 48.895,87.63 h1.4
  text "PH13" at 95.25,87.63 h1.4
  text "3V3" at 122.555,87.63 h1.4
  text "PG8" at 70.468,87.481 h1.4
  text "3V3 AO" at 19.305,86.434 h1.6
  text "DFSDM/NOR" at 132.842,86.191 h1.4 r90
  text "D" at 2.032,85.979 h1.6
  text "TRACE" at 148.487,85.612 h2 r90
  text "CHGR" at 0.381,83.49 h1.6
  text "Power Source" at 0.635,81.123 h1.6
  text "JTAG" at 159.244,80.359 h2 r90
  text "5V EXT" at 13.006,75.9 h1.6
  text "MIPI10" at 148.154,71.388 h2 r90
  text "SDRAM" at 87.154,68.363 h1.4
  text "SRAM" at 61.354,67.363 h1.4
  text "Battery" at 29.21,65.024 h2
  text "3V3 STLK" at 27.505,57.557 h1.6
  text "+" at 0.646,53.784 h2
  text "-" at 3.874,53.774 h2
  text "PSU DC 5V" at 5.246,53.184 h2
  text "AUDIO OUT" at 158.7,52.6 h2
  text "5V USB" at 3.5,50.7 h1.6
  text "CTP /" at 140.545,50.625 h2
  text "5V STLK" at 15.937,50.6 h1.6
  text "CHGR" at 3.8,49.4 h1.6
  text "VBAT" at 48.26,49.403 h1.6
  text "LCD PWR" at 138.77,48.85 h2
  text "STLK_NRST" at 24.892,47.625 h1.4 r90
  text "3V3" at 39.37,46.863 h1.6
  text "Battery" at 45.593,46.863 h1.6
  text "WIFI" at 50.795,40.9 h2
  text "AUDIO IN" at 160.5,39.9 h2
  text "STLINK V3" at 10.927,34.857 h2
  text "CAN" at 152.4,28.829 h1.4 r90
  text "MB1331D" at 102.2,27.3 h2
  text "LCD RGB - 3x8" at 77.312,24.756 h2
  text "C" at 75.8,18.2 h5
  text "GND" at 19.264,17.573 h1.4
  text "STLINK V3.0" at 23.828,16.053 h2
  text "MFX" at 106.546,16.002 h2
  text "I2C EXT" at 0.8,15.16 h2
  text "GND" at 132.164,15.091 h1.4
  text "PROG" at 105.784,14.605 h2
  text "PROG" at 26.114,14.578 h2
  text "I" at 67.625,13.1 h10
  text "H" at 73.4,11.4 h15
  text "COM" at 0.505,7.575 h2
  text "CAN" at 164.075,5.975 h2
  text "F" at 5.8,5.5 h6
  text "E" at 23,4.5 h8
  text "G" at 5.5,2 h5
  text "USB / OTG FS" at 156.5,0.7 h2
  text "ADC CHANNEL" at 10.775,0.57 h2
  text "RESET" at 71.845,0.41 h2
  text "WKUP" at 89.63,0.4 h2
  text "TAMP" at 107.94,0.4 h2
  text "JOYSTICK" at 122.085,0.4 h2
Bottom Overlay:
  lines w0.127: 28.702,67.691 28.702,69.723 34.671,69.723 34.671,67.691 28.702,67.691 ; 136.9,60.691 149.8,60.691 149.8,62.723 136.9,62.723 136.9,60.691 ; 159.766,154.94 164.338,154.94 164.338,156.718 159.766,156.718 159.766,154.94
  text "uSD1" at 164.084,155.194 h2
  text "Battery" at 34.417,68.199 h2
  text "AUDIO CODEC" at 149.6,61.2 h2
  text "MB1331D" at 84.475,52.075 h2
Top Solder:
  rectangle: 145,169.425 153.5,171.175
Bottom Solder:
  rectangle: 145,169.425 153.5,171.175
M1-Board Shape:
  lines w0.254: 0,1.7 0,171.25 ; 0,1.725 ccw(c1.725,1.725) 1.725,0 40.4,0.01 40.4,10.2 65.4,10.2 65.4,0.01 167.333,0 ccw(c167.333,1.667) 169,1.667 169,171.275 ccw(c167.275,171.275) 167.275,173 ; 0,171.275 cw(c1.725,171.275) 1.725,173 ; 1.715,173 167.24,173
M5-Top Constraints:
  lines w0.127: 152.573,146.658 152.573,135.128 159.563,128.138 167.573,128.138 168.573,129.138 168.573,172.138 168.073,172.638 140.073,172.638 139.573,172.138 139.573,151.638 140.473,150.738 148.493,150.738 cw(c148.498,146.663) 152.573,146.663
  lines w0.2: 183.69,2.247 183.69,15.762 ; 183.69,5.762 273.19,5.762 ; 183.69,9.262 273.19,9.262 ; 183.69,22.059 183.69,35.574 ; 183.69,25.574 273.19,25.574 ; 183.69,29.074 273.19,29.074 ; 183.69,41.998 183.69,55.513 ; 183.69,45.513 273.19,45.513 ; 183.69,49.013 273.19,49.013 ; 183.695,2.247 273.195,2.247 ; 183.695,5.747 273.195,5.747 ; 183.695,22.059 273.195,22.059 ; 183.695,25.559 273.195,25.559 ; 183.695,41.998 273.195,41.998 ; 183.695,45.498 273.195,45.498 ; 184.44,17.512 209.44,17.512 ; 184.44,37.324 209.44,37.324 ; 184.44,57.263 209.44,57.263 ; 204.19,2.247 204.19,15.762 ; 204.19,22.059 204.19,35.574 ; 204.19,41.998 204.19,55.513 ; 214.69,2.247 214.69,15.762 ; 214.69,22.059 214.69,35.574 ; 214.69,41.998 214.69,55.513 ; 228.19,2.247 228.19,15.762 ; 228.19,22.059 228.19,35.574 ; 228.19,41.998 228.19,55.513 ; 245.19,2.247 245.19,15.762 ; 245.19,22.059 245.19,35.574 ; 245.19,41.998 245.19,55.513 ; 262.19,2.247 262.19,15.762 ; 262.19,22.059 262.19,35.574 ; 262.19,41.998 262.19,55.513 ; 273.19,2.247 273.19,15.762 ; 273.19,22.059 273.19,35.574 ; 273.19,41.998 273.19,55.513 ; 183.69,15.762 204.19,15.762 ; 183.69,15.762 183.69,21.012 273.19,21.012 273.19,15.762 ; 183.69,15.762 183.69,15.762 ; 183.69,35.574 204.19,35.574 ; 183.69,35.574 183.69,40.824 273.19,40.824 273.19,35.574 ; 183.69,35.574 183.69,35.574 ; 183.69,55.513 183.69,55.513 ; 183.69,55.513 183.69,60.763 273.19,60.763 273.19,55.513 ; 183.69,55.513 204.19,55.513 ; 204.19,15.762 214.69,15.762 ; 204.19,35.574 214.69,35.574 ; 204.19,55.513 214.69,55.513 ; 214.69,15.762 228.19,15.762 ; 214.69,35.574 228.19,35.574 ; 214.69,55.513 228.19,55.513 ; 228.19,15.762 245.19,15.762 ; 228.19,35.574 245.19,35.574 ; 228.19,55.513 245.19,55.513 ; 245.19,15.762 262.19,15.762 ; 245.19,35.574 262.19,35.574 ; 245.19,55.513 262.19,55.513 ; 262.19,15.762 273.19,15.762 ; 262.19,35.574 273.19,35.574 ; 262.19,55.513 273.19,55.513
  lines w0.254: 37.34,22.185 ccw(c37.375,20.915) 37.351,19.645 ; 37.34,22.188 119.343,22.188 ; 37.383,19.648 119.343,19.648 ; 102.21,25.75 ccw(c102.245,24.48) 102.221,23.21 ; 102.267,23.204 133.733,23.204 ccw(c133.697,24.474) 133.722,25.744 ; 102.267,25.744 133.733,25.744 ; 119.259,22.185 cw(c119.235,20.915) 119.27,19.645 ; 131.25,100.6 131.25,126.6 168.75,126.6 168.75,100.6 131.25,100.6
  lines w0.5: 2,135.075 2,18 167,18 167,135.075 ; 2,135.251 167,135.251 ; 21,18.024 21,135.151 ; 21,91.124 148,91.124 ; 148,18.124 148,135.251
  text "MB1379 - CAMERA" at 155.829,171.196 h1.52
  text "MB1063 - 5.7\"" at 137.88,133.47 h1.52
  text "MB1370 - 7\"" at 152.235,133.47 h1.52
  text "MB1242 OCSPI" at 156.718,125.095 h1.52
  text "MB1046 - 4.3\"" at 134.2,89.4 h1.52
  text "IMPEDANCE TABLE    SDRAM, SD CARD, ULPI, CAMERA" at 184.44,57.763 h3
  text "LAYER" at 188.69,52.763 h3
  text "TRACE" at 204.94,52.763 h3
  text "SPACING" at 215.44,52.763 h3
  text "IMPEDANCE" at 228.94,52.763 h3
  text "IMPEDANCE" at 245.94,52.763 h3
  text "TOL." at 264.69,52.763 h3
  text "(mm)" at 218.765,50.288 h2.5
  text "(mm)" at 206.94,50.238 h2.5
  text "(Single ended)" at 229.44,50.013 h2.5
  text "(Differential)" at 247.19,50.013 h2.5
  text "+/- 15%" at 263.745,46.373 h3
  text "0.127" at 205.915,46.288 h3
  text "TOP/BOTTOM" at 184.92,46.248 h3
  text "n/a" at 217.94,46.263 h3
  text "50 ohm" at 232.295,46.198 h3
  text "n/a" at 251.845,46.148 h3
  text "+/- 15%" at 263.75,42.858 h3
  text "0.102" at 205.92,42.773 h3
  text "n/a" at 217.945,42.748 h3
  text "LAYER 3" at 186.865,42.713 h3
  text "50 ohm" at 232.3,42.683 h3
  text "n/a" at 251.85,42.633 h3
  text "WIFI INTERPOSER" at 45.7,37.8 h1.52
  text "IMPEDANCE TABLE    OCSPI CLKP/N" at 184.44,37.443 h3
  text "LAYER" at 188.69,32.824 h3
  text "TRACE" at 204.94,32.824 h3
  text "SPACING" at 215.44,32.824 h3
  text "IMPEDANCE" at 228.94,32.824 h3
  text "IMPEDANCE" at 245.94,32.824 h3
  text "TOL." at 264.69,32.824 h3
  text "(mm)" at 218.765,30.349 h2.5
  text "(mm)" at 206.94,30.299 h2.5
  text "(Single ended)" at 229.44,30.074 h2.5
  text "(Differential)" at 247.19,30.074 h2.5
  text "+/- 15%" at 263.745,26.434 h3
  text "0.130" at 205.915,26.349 h3
  text "TOP/BOTTOM" at 184.92,26.309 h3
  text "251" at 217.94,26.324 h3
  text "n/a" at 232.295,26.259 h3
  text "100 ohm" at 248.381,26.21 h3
  text "+/- 15%" at 263.75,22.919 h3
  text "0.104" at 205.92,22.834 h3
  text "277" at 217.945,22.809 h3
  text "LAYER 3" at 186.865,22.774 h3
  text "100 ohm" at 248.381,22.781 h3
  text "n/a" at 232.3,22.744 h3
  text "IMPEDANCE TABLE   USB FS, USB HS USER, USB HS STLINK" at 184.44,18.012 h3
  text "LAYER" at 188.69,13.012 h3
  text "TRACE" at 204.94,13.012 h3
  text "SPACING" at 215.44,13.012 h3
  text "IMPEDANCE" at 228.94,13.012 h3
  text "IMPEDANCE" at 245.94,13.012 h3
  text "TOL." at 264.69,13.012 h3
  text "(mm)" at 218.765,10.537 h2.5
  text "(mm)" at 206.94,10.487 h2.5
  text "(Single ended)" at 229.44,10.262 h2.5
  text "(Differential)" at 247.19,10.262 h2.5
  text "+/- 15%" at 263.745,6.622 h3
  text "0.155" at 205.915,6.537 h3
  text "TOP/BOTTOM" at 184.92,6.497 h3
  text "226" at 217.94,6.512 h3
  text "n/a" at 232.295,6.447 h3
  text "90 ohm" at 248.381,6.271 h3
  text "+/- 15%" at 263.75,3.107 h3
  text "0.130" at 205.92,3.022 h3
  text "251" at 217.945,2.997 h3
  text "LAYER 3" at 186.865,2.962 h3
  text "90 ohm" at 248.381,2.969 h3
  text "n/a" at 232.3,2.932 h3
